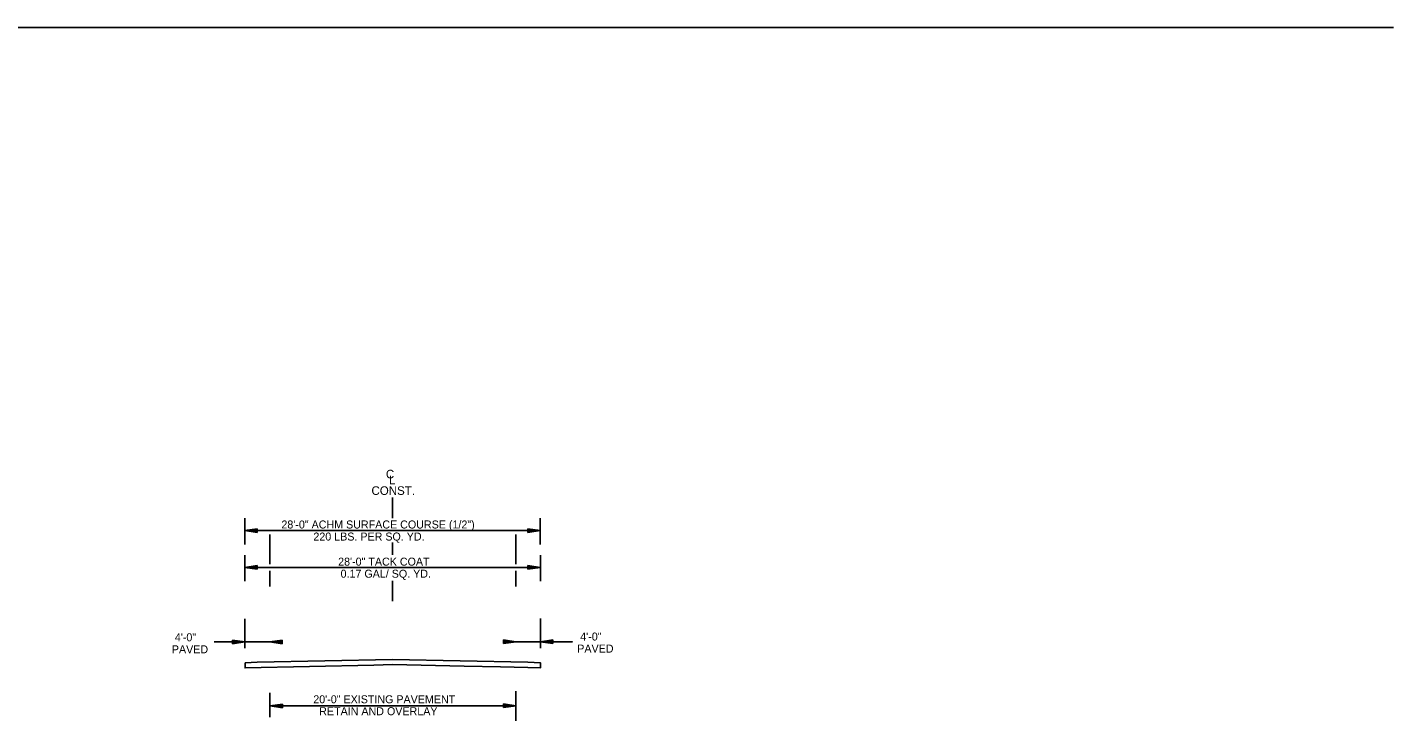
# Model space of a CAD drawing. Extents: x 1373719 to 1374161, y 379835 to 380167.
# Drawn here: x 1373935.3 to 1374046.4, y 379842.8 to 379899.1 of the extents above; entities that cross this region are included whole.
import ezdxf

# ---------------------------------------------------------------- set-up
doc = ezdxf.new("R2010")
doc.units = 0
for name, color, linetype in [('DATE', 7, 'Continuous'), ('SIGNATURE', 7, 'Continuous'), ('Text 1', 7, 'Continuous')]:
    doc.layers.add(name, color=color, linetype=linetype)

msp = doc.modelspace()

# ---------------------------------------------------------------- linework, layer by layer
at = {"layer": 'DATE'}
msp.add_line((1373870.36, 379899.14), (1374046.36, 379899.14), dxfattribs=at)
at = {"layer": 'SIGNATURE'}
msp.add_lwpolyline([(1373953.04, 379847.49), (1373953.04, 379847.07), (1373963.51, 379847.3), (1373965.01, 379847.33), (1373970.85, 379847.22), (1373973.8, 379847.16), (1373976.01, 379847.11), (1373977.04, 379847.07), (1373977.04, 379847.49), (1373976.02, 379847.53), (1373965.02, 379847.75), (1373954.02, 379847.53)], close=True, dxfattribs=at)
at = {"layer": 'Text 1'}
for p, q in [((1373965.02, 379859.25), (1373965.02, 379860.93)), ((1373953.02, 379859.23), (1373953.02, 379857.11)), ((1373977.02, 379859.23), (1373977.02, 379857.11)), ((1373954.02, 379858.38), (1373953.02, 379858.23)), ((1373953.02, 379858.23), (1373977.02, 379858.23)), ((1373954.02, 379858.08), (1373953.02, 379858.23)), ((1373954.02, 379858.35), (1373953.18, 379858.23)), ((1373954.02, 379858.1), (1373953.18, 379858.23)), ((1373954.02, 379858.33), (1373953.36, 379858.23)), ((1373954.02, 379858.13), (1373953.36, 379858.23)), ((1373954.02, 379858.3), (1373953.52, 379858.23)), ((1373954.02, 379858.15), (1373953.52, 379858.23)), ((1373954.02, 379858.28), (1373953.69, 379858.23)), ((1373954.02, 379858.18), (1373953.69, 379858.23)), ((1373954.02, 379858.25), (1373953.86, 379858.23)), ((1373954.02, 379858.2), (1373953.86, 379858.23)), ((1373954.02, 379858.08), (1373954.02, 379858.38)), ((1373955.04, 379855.49), (1373955.04, 379857.9)), ((1373975.04, 379855.49), (1373975.04, 379857.9)), ((1373976.02, 379858.38), (1373977.02, 379858.23)), ((1373976.02, 379858.38), (1373976.02, 379858.08)), ((1373976.02, 379858.35), (1373976.85, 379858.23)), ((1373976.02, 379858.33), (1373976.68, 379858.23)), ((1373976.02, 379858.3), (1373976.51, 379858.23)), ((1373976.02, 379858.27), (1373976.34, 379858.23)), ((1373976.02, 379858.25), (1373976.18, 379858.23)), ((1373976.02, 379858.08), (1373977.02, 379858.23)), ((1373976.02, 379858.18), (1373976.34, 379858.23)), ((1373976.02, 379858.13), (1373976.68, 379858.23)), ((1373976.02, 379858.1), (1373976.85, 379858.23)), ((1373976.02, 379858.15), (1373976.51, 379858.23)), ((1373976.02, 379858.2), (1373976.18, 379858.23)), ((1373965.02, 379856.26), (1373965.02, 379857.27)), ((1373953.02, 379856.23), (1373953.02, 379854.11)), ((1373977.04, 379856.22), (1373977.04, 379854.11)), ((1373954.02, 379855.38), (1373953.02, 379855.23)), ((1373954.02, 379855.08), (1373953.02, 379855.23)), ((1373953.02, 379855.23), (1373977.02, 379855.23)), ((1373954.02, 379855.35), (1373953.18, 379855.23)), ((1373954.02, 379855.1), (1373953.18, 379855.23)), ((1373954.02, 379855.33), (1373953.36, 379855.23)), ((1373954.02, 379855.13), (1373953.36, 379855.23)), ((1373954.02, 379855.3), (1373953.52, 379855.23)), ((1373954.02, 379855.15), (1373953.52, 379855.23)), ((1373954.02, 379855.28), (1373953.69, 379855.23)), ((1373954.02, 379855.18), (1373953.69, 379855.23)), ((1373954.02, 379855.25), (1373953.86, 379855.23)), ((1373954.02, 379855.2), (1373953.86, 379855.23)), ((1373954.02, 379855.08), (1373954.02, 379855.38)), ((1373955.04, 379853.69), (1373955.04, 379854.95)), ((1373975.04, 379853.69), (1373975.04, 379854.95)), ((1373976.02, 379855.38), (1373977.02, 379855.23)), ((1373976.02, 379855.38), (1373976.02, 379855.08)), ((1373976.02, 379855.35), (1373976.85, 379855.23)), ((1373976.02, 379855.33), (1373976.68, 379855.23)), ((1373976.02, 379855.3), (1373976.51, 379855.23)), ((1373976.02, 379855.27), (1373976.34, 379855.23)), ((1373976.02, 379855.25), (1373976.18, 379855.23)), ((1373976.02, 379855.08), (1373977.02, 379855.23)), ((1373976.02, 379855.18), (1373976.34, 379855.23)), ((1373976.02, 379855.13), (1373976.68, 379855.23)), ((1373976.02, 379855.1), (1373976.85, 379855.23)), ((1373976.02, 379855.15), (1373976.51, 379855.23)), ((1373976.02, 379855.2), (1373976.18, 379855.23)), ((1373965.02, 379852.49), (1373965.02, 379854.15)), ((1373953.03, 379851.06), (1373953.03, 379848.68)), ((1373977.04, 379848.68), (1373977.04, 379851.07)), ((1373950.52, 379849.19), (1373955.04, 379849.18)), ((1373952.02, 379849.33), (1373953.02, 379849.18)), ((1373952.02, 379849.33), (1373952.02, 379849.03)), ((1373952.02, 379849.31), (1373952.86, 379849.18)), ((1373952.02, 379849.28), (1373952.68, 379849.18)), ((1373952.02, 379849.26), (1373952.52, 379849.18)), ((1373952.02, 379849.23), (1373952.35, 379849.18)), ((1373952.02, 379849.21), (1373952.18, 379849.18)), ((1373952.02, 379849.03), (1373953.02, 379849.18)), ((1373952.02, 379849.13), (1373952.35, 379849.18)), ((1373952.02, 379849.08), (1373952.68, 379849.18)), ((1373952.02, 379849.06), (1373952.86, 379849.18)), ((1373952.02, 379849.11), (1373952.52, 379849.18)), ((1373952.02, 379849.16), (1373952.18, 379849.18)), ((1373956.04, 379849.33), (1373955.04, 379849.18)), ((1373956.04, 379849.03), (1373955.04, 379849.18)), ((1373956.04, 379849.31), (1373955.21, 379849.18)), ((1373956.04, 379849.06), (1373955.21, 379849.18)), ((1373956.04, 379849.28), (1373955.38, 379849.18)), ((1373956.04, 379849.08), (1373955.38, 379849.18)), ((1373956.04, 379849.26), (1373955.55, 379849.18)), ((1373956.04, 379849.11), (1373955.55, 379849.18)), ((1373956.04, 379849.23), (1373955.72, 379849.18)), ((1373956.04, 379849.13), (1373955.72, 379849.18)), ((1373956.04, 379849.21), (1373955.89, 379849.18)), ((1373956.04, 379849.16), (1373955.89, 379849.18)), ((1373956.04, 379849.03), (1373956.04, 379849.33)), ((1373974.04, 379849.34), (1373975.04, 379849.19)), ((1373974.04, 379849.34), (1373974.04, 379849.04)), ((1373974.04, 379849.31), (1373974.87, 379849.19)), ((1373974.04, 379849.29), (1373974.7, 379849.19)), ((1373974.04, 379849.26), (1373974.54, 379849.19)), ((1373974.04, 379849.24), (1373974.37, 379849.19)), ((1373974.04, 379849.21), (1373974.2, 379849.19)), ((1373974.04, 379849.04), (1373975.04, 379849.19)), ((1373974.04, 379849.14), (1373974.37, 379849.19)), ((1373974.04, 379849.09), (1373974.7, 379849.19)), ((1373974.04, 379849.06), (1373974.87, 379849.19)), ((1373974.04, 379849.11), (1373974.54, 379849.19)), ((1373974.04, 379849.16), (1373974.2, 379849.19)), ((1373978.04, 379849.34), (1373977.04, 379849.19)), ((1373978.04, 379849.04), (1373977.04, 379849.19)), ((1373977.04, 379849.19), (1373977.04, 379849.19)), ((1373978.04, 379849.32), (1373977.21, 379849.19)), ((1373978.04, 379849.07), (1373977.21, 379849.19)), ((1373978.04, 379849.29), (1373977.38, 379849.19)), ((1373978.04, 379849.09), (1373977.38, 379849.19)), ((1373978.04, 379849.26), (1373977.55, 379849.19)), ((1373978.04, 379849.12), (1373977.55, 379849.19)), ((1373978.04, 379849.24), (1373977.72, 379849.19)), ((1373978.04, 379849.14), (1373977.72, 379849.19)), ((1373978.04, 379849.21), (1373977.89, 379849.19)), ((1373978.04, 379849.17), (1373977.89, 379849.19)), ((1373978.04, 379849.04), (1373978.04, 379849.34)), ((1373975.04, 379843.99), (1373955.04, 379843.99)), ((1373956.08, 379844.13), (1373955.08, 379843.98)), ((1373956.08, 379843.83), (1373955.08, 379843.98)), ((1373956.08, 379844.11), (1373955.24, 379843.98)), ((1373956.08, 379843.86), (1373955.24, 379843.98)), ((1373956.08, 379844.08), (1373955.42, 379843.98)), ((1373956.08, 379843.88), (1373955.42, 379843.98)), ((1373956.08, 379844.06), (1373955.58, 379843.98)), ((1373956.08, 379843.91), (1373955.58, 379843.98)), ((1373956.08, 379844.03), (1373955.75, 379843.98)), ((1373956.08, 379843.93), (1373955.75, 379843.98)), ((1373956.08, 379844.01), (1373955.92, 379843.98)), ((1373956.08, 379843.96), (1373955.92, 379843.98)), ((1373956.08, 379843.83), (1373956.08, 379844.13)), ((1373974.04, 379844.14), (1373975.04, 379843.99)), ((1373974.04, 379844.14), (1373974.04, 379843.84)), ((1373974.04, 379844.11), (1373974.88, 379843.99)), ((1373974.04, 379844.09), (1373974.71, 379843.99)), ((1373974.04, 379844.06), (1373974.54, 379843.99)), ((1373974.04, 379844.04), (1373974.37, 379843.99)), ((1373974.04, 379844.01), (1373974.2, 379843.99)), ((1373974.04, 379843.84), (1373975.04, 379843.99)), ((1373974.04, 379843.94), (1373974.37, 379843.99)), ((1373974.04, 379843.89), (1373974.71, 379843.99)), ((1373974.04, 379843.86), (1373974.88, 379843.99)), ((1373974.04, 379843.91), (1373974.54, 379843.99)), ((1373974.04, 379843.97), (1373974.2, 379843.99)), ((1373974.37, 379843.93), (1373974.37, 379843.93))]:
    msp.add_line(p, q, dxfattribs=at)
for points in [[(1373975.04, 379849.19), (1373979.64, 379849.19), (1373979.64, 379849.19)], [(1373955.04, 379843.06), (1373955.04, 379845.03)], [(1373975.04, 379842.77), (1373975.04, 379845.18)]]:
    msp.add_lwpolyline(points, dxfattribs=at)

# ---------------------------------------------------------------- texts
for s, height, p in [('C', 0.7, (1373964.48, 379862.47)), ('L', 0.7, (1373964.73, 379861.99)), ('CONST.', 0.7, (1373963.31, 379861.13)), ('28\'-0" ACHM SURFACE COURSE (1/2")', 0.65, (1373955.99, 379858.4)), ('220 LBS. PER SQ. YD.', 0.65, (1373958.59, 379857.42)), ('28\'-0" TACK COAT', 0.65, (1373960.6, 379855.38)), ('0.17 GAL/ SQ. YD.', 0.65, (1373960.8, 379854.4)), (' 4\'-0" ', 0.65, (1373947.09, 379849.23)), (' 4\'-0" ', 0.65, (1373980.03, 379849.29)), ('PAVED', 0.65, (1373947.09, 379848.25)), ('PAVED', 0.65, (1373980.03, 379848.31)), ('20\'-0" EXISTING PAVEMENT', 0.65, (1373958.58, 379844.19)), ('  RETAIN AND OVERLAY', 0.65, (1373958.58, 379843.22))]:
    msp.add_text(s, height=height, dxfattribs=at).set_placement(p)

doc.saveas('drawing.dxf')
